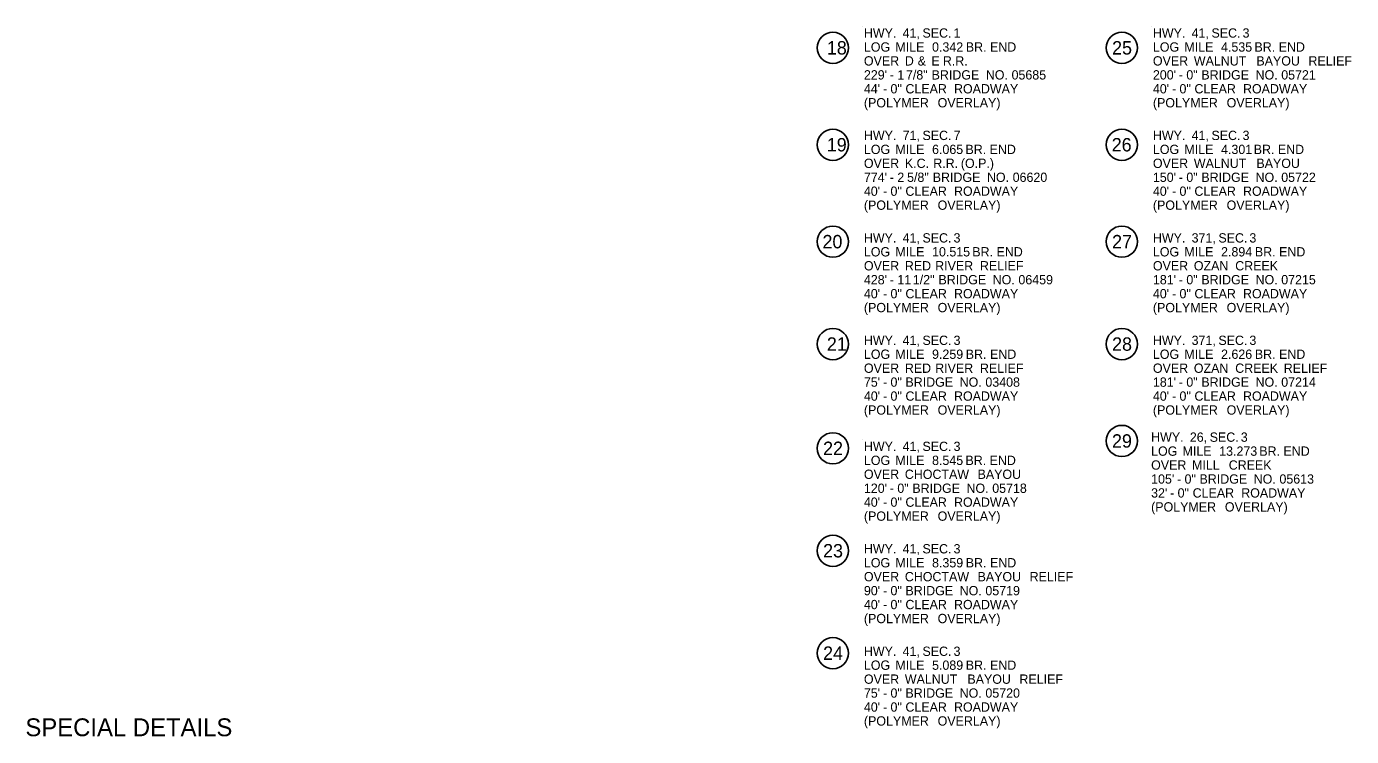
# Model space of a CAD drawing. Extents: x 3046 to 131673, y -8885 to 10756.
# Drawn here: x 52625 to 70441, y -8885 to 662 of the extents above; entities that cross this region are included whole.
import ezdxf

# ---------------------------------------------------------------- set-up
doc = ezdxf.new("R2010")
doc.units = 0
for name, color, linetype in [('Default', 7, 'Continuous'), ('R_Annotation', 7, 'Continuous'), ('R_Border Notes', 7, 'Continuous')]:
    doc.layers.add(name, color=color, linetype=linetype)

msp = doc.modelspace()

# ---------------------------------------------------------------- linework, layer by layer
at = {"layer": 'R_Annotation'}
for centre in [(63468, 375), (67354, 375), (63468, -928), (67354, -928), (63468, -2231), (67354, -2231), (63468, -3608), (67354, -3608), (63468, -5010), (67354, -4911), (63468, -6387), (63468, -7764)]:
    msp.add_circle(centre, 210, dxfattribs=at)
at = {"layer": 'R_Border Notes'}
for p, q in [((63861, 662), (63861, 662)), ((67747, 662), (67747, 662)), ((67747, -4797), (67747, -4797)), ((63861, -4896), (63861, -4896))]:
    msp.add_line(p, q, dxfattribs=at)

# ---------------------------------------------------------------- texts
at = {"layer": 'Default'}
for s, p in [('HWY.', (63885, 512)), (' 41,', (64359, 512)), (' SEC.', (64626, 512)), (' 1', (65044, 512)), ('HWY.', (67771, 512)), (' 41,', (68245, 512)), (' SEC.', (68512, 512)), (' 3', (68930, 512)), ('LOG', (63885, 324)), (' MILE', (64262, 324)), (' 0.342', (64755, 324)), (' BR.', (65209, 324)), (' END', (65534, 324)), ('LOG', (67771, 324)), (' MILE', (68148, 324)), (' 4.535', (68641, 324)), (' BR.', (69090, 324)), (' END', (69416, 324)), ('OVER', (63885, 137)), (' D', (64389, 137)), (' &', (64562, 137)), (' E', (64746, 137)), (' R.R.', (64900, 137)), ('OVER', (67771, 137)), (' WALNUT', (68275, 137)), (' BAYOU', (69116, 137)), (' RELIEF', (69816, 137)), ("229'", (63885, -51)), (' -', (64188, -51)), (' 1', (64288, -51)), (' 7/8"', (64404, -51)), (' BRIDGE', (64749, -51)), (' NO.', (65478, -51)), (' 05685', (65824, -51)), ("200'", (67771, -51)), (' -', (68074, -51)), (' 0"', (68174, -51)), (' BRIDGE', (68376, -51)), (' NO.', (69105, -51)), (' 05721', (69450, -51)), ("44'", (63885, -238)), (' 0"', (64196, -238)), (' CLEAR', (64397, -238)), (' ROADWAY', (65050, -238)), ("40'", (67771, -238)), (' 0"', (68082, -238)), (' CLEAR', (68283, -238)), (' ROADWAY', (68936, -238)), ('(POLYMER', (63885, -426)), (' -', (64095, -238)), (' OVERLAY)', (64830, -426)), ('(POLYMER', (67771, -426)), (' -', (67981, -238)), (' OVERLAY)', (68716, -426)), ('HWY.', (63885, -865)), (' 71,', (64359, -865)), (' SEC.', (64626, -865)), (' 7', (65044, -865)), ('HWY.', (67771, -865)), (' 41,', (68245, -865)), (' SEC.', (68512, -865)), (' 3', (68930, -865)), ('LOG', (63885, -1053)), (' MILE', (64262, -1053)), (' 6.065', (64755, -1053)), (' BR.', (65204, -1053)), (' END', (65529, -1053)), ('LOG', (67771, -1053)), (' MILE', (68148, -1053)), (' 4.301', (68641, -1053)), (' BR.', (69080, -1053)), (' END', (69405, -1053)), ('OVER', (63885, -1240)), (' K.C.', (64389, -1240)), (' R.R.', (64771, -1240)), (' (O.P.)', (65142, -1240)), ('OVER', (67771, -1240)), (' WALNUT', (68275, -1240)), (' BAYOU', (69116, -1240)), ("774'", (63885, -1428)), (' -', (64188, -1428)), (' 2', (64288, -1428)), (' 5/8"', (64419, -1428)), (' BRIDGE', (64764, -1428)), (' NO.', (65493, -1428)), (' 06620', (65839, -1428)), ("150'", (67771, -1428)), (' -', (68074, -1428)), (' 0"', (68174, -1428)), (' BRIDGE', (68376, -1428)), (' NO.', (69105, -1428)), (' 05722', (69450, -1428)), ("40'", (63885, -1615)), (' -', (64095, -1615)), (' 0"', (64196, -1615)), (' CLEAR', (64397, -1615)), (' ROADWAY', (65050, -1615)), ("40'", (67771, -1615)), (' -', (67981, -1615)), (' 0"', (68082, -1615)), (' CLEAR', (68283, -1615)), (' ROADWAY', (68936, -1615)), ('(POLYMER', (63885, -1803)), (' OVERLAY)', (64830, -1803)), ('(POLYMER', (67771, -1803)), (' OVERLAY)', (68716, -1803)), ('HWY.', (63885, -2243)), (' 41,', (64359, -2243)), (' SEC.', (64626, -2243)), (' 3', (65044, -2243)), ('HWY.', (67771, -2243)), (' 371,', (68245, -2243)), (' SEC.', (68605, -2243)), (' 3', (69022, -2243)), ('LOG', (63885, -2430)), (' MILE', (64262, -2430)), (' 10.515', (64755, -2430)), (' BR.', (65296, -2430)), (' END', (65622, -2430)), ('LOG', (67771, -2430)), (' MILE', (68148, -2430)), (' 2.894', (68641, -2430)), (' BR.', (69096, -2430)), (' END', (69421, -2430)), ('OVER', (63885, -2618)), (' RED', (64389, -2618)), (' RIVER', (64797, -2618)), (' RELIEF', (65399, -2618)), ('OVER', (67771, -2618)), (' OZAN', (68275, -2618)), (' CREEK', (68831, -2618)), ("428'", (63885, -2805)), (' -', (64188, -2805)), (' 11', (64288, -2805)), (' 1/2"', (64496, -2805)), (' BRIDGE', (64841, -2805)), (' NO.', (65570, -2805)), (' 06459', (65916, -2805)), ("181'", (67771, -2805)), (' -', (68074, -2805)), (' 0"', (68174, -2805)), (' BRIDGE', (68376, -2805)), (' NO.', (69105, -2805)), (' 07215', (69450, -2805)), ("40'", (63885, -2993)), (' -', (64095, -2993)), (' 0"', (64196, -2993)), (' CLEAR', (64397, -2993)), (' ROADWAY', (65050, -2993)), ("40'", (67771, -2993)), (' -', (67981, -2993)), (' 0"', (68082, -2993)), (' CLEAR', (68283, -2993)), (' ROADWAY', (68936, -2993)), ('(POLYMER', (63885, -3180)), (' OVERLAY)', (64830, -3180)), ('(POLYMER', (67771, -3180)), (' OVERLAY)', (68716, -3180)), ('HWY.', (63885, -3620)), (' 41,', (64359, -3620)), (' SEC.', (64626, -3620)), (' 3', (65044, -3620)), ('HWY.', (67771, -3620)), (' 371,', (68245, -3620)), (' SEC.', (68605, -3620)), (' 3', (69022, -3620)), ('LOG', (63885, -3807)), (' MILE', (64262, -3807)), (' 9.259', (64755, -3807)), (' BR.', (65208, -3807)), (' END', (65534, -3807)), ('LOG', (67771, -3807)), (' MILE', (68148, -3807)), (' 2.626', (68641, -3807)), (' BR.', (69095, -3807)), (' END', (69421, -3807)), ('OVER', (63885, -3995)), (' RED', (64389, -3995)), (' RIVER', (64797, -3995)), (' RELIEF', (65399, -3995)), ('OVER', (67771, -3995)), (' OZAN', (68275, -3995)), (' CREEK', (68831, -3995)), (' RELIEF', (69484, -3995)), ("75'", (63885, -4182)), (' 0"', (64196, -4182)), (' BRIDGE', (64397, -4182)), (' NO.', (65126, -4182)), (' 03408', (65472, -4182)), ("181'", (67771, -4182)), (' 0"', (68174, -4182)), (' BRIDGE', (68376, -4182)), (' NO.', (69105, -4182)), (' 07214', (69450, -4182)), ("40'", (63885, -4370)), (' -', (64095, -4182)), (' 0"', (64196, -4370)), (' CLEAR', (64397, -4370)), (' ROADWAY', (65050, -4370)), ("40'", (67771, -4370)), (' -', (68074, -4182)), (' 0"', (68082, -4370)), (' CLEAR', (68283, -4370)), (' ROADWAY', (68936, -4370)), ('(POLYMER', (63885, -4557)), (' -', (64095, -4370)), (' OVERLAY)', (64830, -4557)), ('(POLYMER', (67771, -4557)), (' -', (67981, -4370)), (' OVERLAY)', (68716, -4557)), ('HWY.', (67747, -4922)), (' 26,', (68221, -4922)), (' SEC.', (68488, -4922)), (' 3', (68906, -4922)), ('HWY.', (63885, -5046)), (' 41,', (64359, -5046)), (' SEC.', (64626, -5046)), (' 3', (65044, -5046)), ('LOG', (67747, -5110)), (' MILE', (68123, -5110)), (' 13.273', (68616, -5110)), (' BR.', (69155, -5110)), (' END', (69480, -5110)), ('LOG', (63885, -5234)), (' MILE', (64262, -5234)), (' 8.545', (64755, -5234)), (' BR.', (65204, -5234)), (' END', (65529, -5234)), ('OVER', (63885, -5421)), (' CHOCTAW', (64389, -5421)), (' BAYOU', (65367, -5421)), ('OVER', (67747, -5297)), (' MILL', (68251, -5297)), (' CREEK', (68744, -5297)), ("120'", (63885, -5609)), (' 0"', (64288, -5609)), (' BRIDGE', (64490, -5609)), (' NO.', (65218, -5609)), (' 05718', (65564, -5609)), ("105'", (67747, -5485)), (' -', (68049, -5485)), (' 0"', (68150, -5485)), (' BRIDGE', (68351, -5485)), (' NO.', (69080, -5485)), (' 05613', (69426, -5485)), ("40'", (63885, -5796)), (' -', (64188, -5609)), (' 0"', (64196, -5796)), (' CLEAR', (64397, -5796)), (' ROADWAY', (65050, -5796)), ("32'", (67747, -5672)), (' -', (67957, -5672)), (' 0"', (68057, -5672)), (' CLEAR', (68259, -5672)), (' ROADWAY', (68912, -5672)), ('(POLYMER', (63885, -5984)), (' -', (64095, -5796)), (' OVERLAY)', (64830, -5984)), ('(POLYMER', (67747, -5860)), (' OVERLAY)', (68692, -5860)), ('HWY.', (63885, -6423)), (' 41,', (64359, -6423)), (' SEC.', (64626, -6423)), (' 3', (65044, -6423)), ('LOG', (63885, -6611)), (' MILE', (64262, -6611)), (' 8.359', (64755, -6611)), (' BR.', (65208, -6611)), (' END', (65534, -6611)), ('OVER', (63885, -6798)), (' CHOCTAW', (64389, -6798)), (' BAYOU', (65367, -6798)), (' RELIEF', (66067, -6798)), ("90'", (63885, -6986)), (' -', (64095, -6986)), (' 0"', (64196, -6986)), (' BRIDGE', (64397, -6986)), (' NO.', (65126, -6986)), (' 05719', (65472, -6986)), ("40'", (63885, -7173)), (' -', (64095, -7173)), (' 0"', (64196, -7173)), (' CLEAR', (64397, -7173)), (' ROADWAY', (65050, -7173)), ('(POLYMER', (63885, -7361)), (' OVERLAY)', (64830, -7361)), ('HWY.', (63885, -7801)), (' 41,', (64359, -7801)), (' SEC.', (64626, -7801)), (' 3', (65044, -7801)), ('LOG', (63885, -7988)), (' MILE', (64262, -7988)), (' 5.089', (64755, -7988)), (' BR.', (65208, -7988)), (' END', (65534, -7988)), ('OVER', (63885, -8176)), (' WALNUT', (64389, -8176)), (' BAYOU', (65230, -8176)), (' RELIEF', (65930, -8176)), ("75'", (63885, -8363)), (' -', (64095, -8363)), (' 0"', (64196, -8363)), (' BRIDGE', (64397, -8363)), (' NO.', (65126, -8363)), (' 05720', (65472, -8363)), ("40'", (63885, -8551)), (' -', (64095, -8551)), (' 0"', (64196, -8551)), (' CLEAR', (64397, -8551)), (' ROADWAY', (65050, -8551)), ('(POLYMER', (63885, -8738)), (' OVERLAY)', (64830, -8738))]:
    msp.add_text(s, height=125, rotation=360, dxfattribs=at).set_placement(p)
at = {"layer": 'R_Annotation'}
for s, height, p in [('18', 180, (63387, 285)), ('25', 180, (67222, 285)), ('19', 180, (63386, -1018)), ('26', 180, (67217, -1018)), ('20', 180, (63328, -2321)), ('27', 180, (67222, -2321)), ('21', 180, (63387, -3698)), ('28', 180, (67222, -3698)), ('22', 180, (63336, -5100)), ('29', 180, (67221, -5001)), ('23', 180, (63336, -6477)), ('24', 180, (63336, -7854)), ('SPECIAL DETAILS', 240, (52610, -8881))]:
    msp.add_text(s, height=height, dxfattribs=at).set_placement(p)

doc.saveas('drawing.dxf')
